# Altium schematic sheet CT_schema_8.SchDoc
size 274 x 160 mm
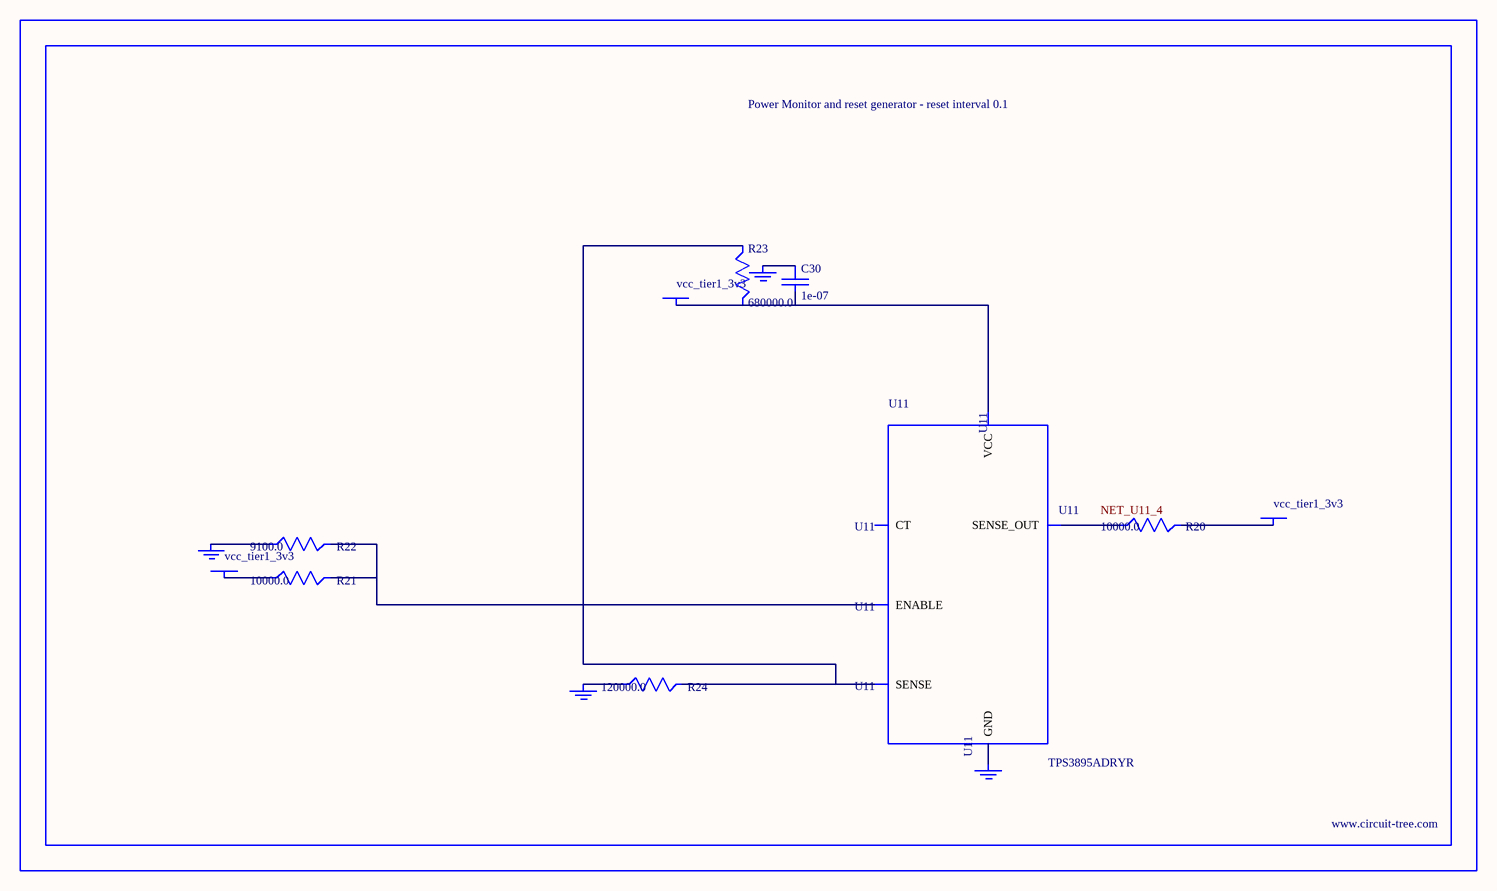
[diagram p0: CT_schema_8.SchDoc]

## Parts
BORDER7  (no value)
C30  1e-07  [C0402]
GND_INSTANCE_7_0  (no value)
GND_INSTANCE_7_1  (no value)
GND_INSTANCE_7_2  (no value)
GND_INSTANCE_7_3  (no value)
POWER_INSTANCE_7_0  vcc_tier1_3v3
POWER_INSTANCE_7_1  vcc_tier1_3v3
POWER_INSTANCE_7_2  vcc_tier1_3v3
R20  10000.0  [R0603]
R21  10000.0  [R0603]
R22  9100.0  [R0603]
R23  680000.0  [R0603]
R24  120000.0  [R0603]
U11  TPS3895ADRYR  [SON-6]

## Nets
NetC30_1: C30.1 GND_INSTANCE_7_2.0(GND)
NetC30_2: C30.2 POWER_INSTANCE_7_2.0(PWR) R23.2 U11.6(VCC)
NetGND_INSTANCE_7_0_0: GND_INSTANCE_7_0.0(GND) R22.1
NetGND_INSTANCE_7_1_0: GND_INSTANCE_7_1.0(GND) R24.1
NetGND_INSTANCE_7_3_0: GND_INSTANCE_7_3.0(GND) U11.2(GND)
NetPOWER_INSTANCE_7_0_0: POWER_INSTANCE_7_0.0(PWR) R21.1
NetPOWER_INSTANCE_7_1_0: POWER_INSTANCE_7_1.0(PWR) R20.2
NetR20_1: R20.1 U11.4(SENSE_OUT)
NetR21_2: R21.2 R22.2 U11.1(ENABLE)
NetR23_1: R23.1 R24.2 U11.3(SENSE)

Not connected (* = marked no-connect by the designer): U11 5(CT)

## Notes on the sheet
- Labels drawn without touching a wire or pin: NET_U11_4

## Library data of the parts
BORDER7 = BORDER_PAGE7
C30 = C0402C104K3RACTU
GND_INSTANCE_7_0-GND_INSTANCE_7_3 = GND
POWER_INSTANCE_7_0-POWER_INSTANCE_7_2 = PWR
R20 R21 = RC0603JR-0710KL
R22 = RC0603JR-079K1L
R23 = RC0603JR-07680KL
R24 = RC0603JR-07120KL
